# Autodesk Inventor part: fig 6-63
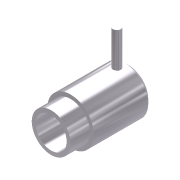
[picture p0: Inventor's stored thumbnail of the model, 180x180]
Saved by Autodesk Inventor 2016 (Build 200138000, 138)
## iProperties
Shininess: 77.0
Angle Display Precision: 2
Document Length Units: 11269
Document Angle Units: 11279
Document Time Units: 11290
Document Mass Units: 11283
Document Length Units Precision: 3
Document Angle Units Precision: 2
Compacted: True
Created: 2001-12
Part Number: fig 6-63
Document SubType Name: Modeling
Designer: Renu Muthoo
Density: 1 g/cm^3
Material: Generic
Appearance: Metal-AL-6061 (Polished)
Density: 0.0
Volumn: 0.0
Area: 0.0
PropertySet Name: Model Information
Control State: 0
Master: False
Checked Out: False
Author: Renu Muthoo
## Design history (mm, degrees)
sketch "Sketch2"
  geometry: L1 (-9.573, -4.327)-(-9.573, -5.327); L2 (-9.573, -5.327)-(-4.573, -5.327); L3 (-4.573, -5.327)-(-4.573, -6.327); L4 (-4.573, -6.327)-(9.427, -6.327); L5 (9.427, -6.327)-(10.427, -5.327); L6 (10.427, -5.327)-(10.427, -4.327); L7 (10.427, -4.327)-(-9.573, -4.327); L8 (-13.687, -0.327)-(14, -0.327)
  constraints: 16 end point, 5 parallel, 1 perpendicular, 1 vertical
  dimensions: "d9" = 20 distance of L6.end L1.start; "d10" = 5 distance of L1.end L2.end; "d11" = 12 diameter of L4 L8; "d12" = 10 diameter of L2 L8; "d13" = 8 diameter of L7 L8; "d14" = 45 deg angle of L5 L4; "d15" = 1 horizontal distance of L5.end L4.end
revolve "Revolution2" sketch "Sketch2" stored, may be unused: angle "d16" = 90 deg
workplane "Work Plane1"
workplane "Work Plane2"
sketch "Sketch3"
  geometry: L1 (-4, 8)-(4, 8) reference; C1 r 1 at (-0.098, 5)
  constraints: 1 centre point
  dimensions: "d18" = 3 distance from line of L1 C1.centre; "d19" = 2 diameter of C1
extrude "Extrusion1" join sketch "Sketch3" distance "d20" = 10; taper "d21" = 0 deg
body "Solid1"
other parameters: "d17" = -1
